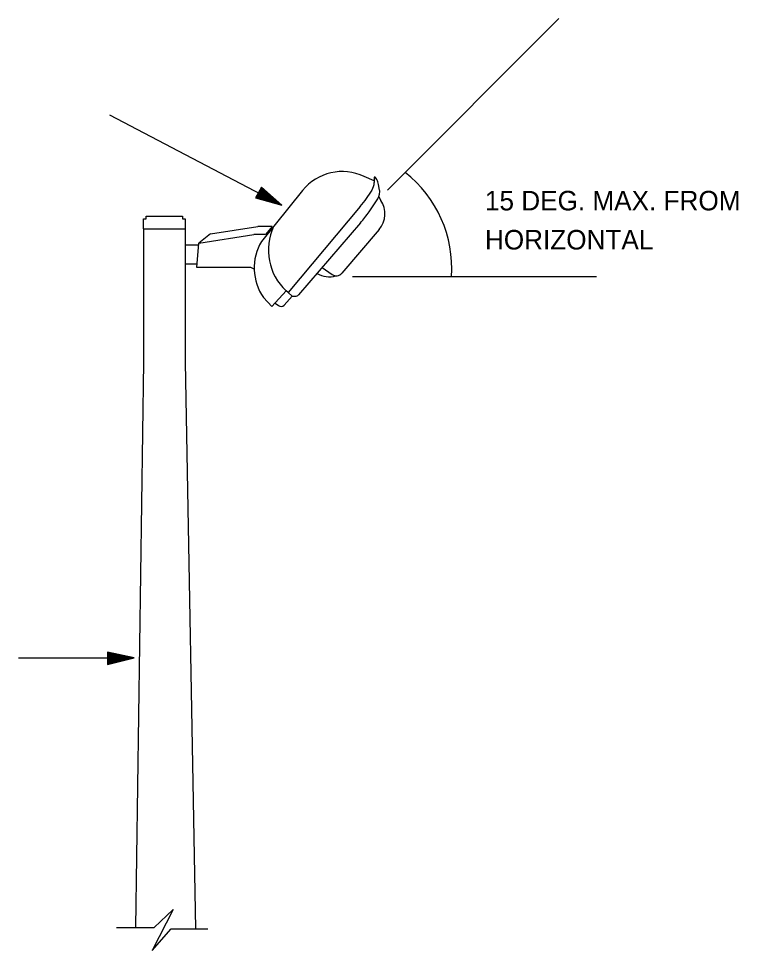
# Model space of a CAD drawing. Extents: x 9989.4 to 10000.1, y 10000.3 to 10010.3.
# Drawn here: x 9997.851 to 10000.06, y 10007.312 to 10010.173 of the extents above; entities that cross this region are included whole.
import ezdxf

# ---------------------------------------------------------------- set-up
doc = ezdxf.new("R2010")
doc.units = 0
for name, color, linetype in [('DETL-DIMS', 7, 'Continuous'), ('DETL-LINE', 7, 'Continuous'), ('DETL-NOTE', 7, 'Continuous')]:
    doc.layers.add(name, color=color, linetype=linetype)

msp = doc.modelspace()

# ---------------------------------------------------------------- linework, layer by layer
at = {"layer": 'DETL-DIMS'}
for p, q in [((9998.9831, 10009.6462), (9999.5096, 10010.1727)), ((9998.1296, 10009.877), (9998.6591, 10009.6003)), ((9998.8759, 10009.3805), (9999.625, 10009.3805)), ((9997.8507, 10008.21), (9998.2057, 10008.21))]:
    msp.add_line(p, q, dxfattribs=at)
for points in [[(9998.5776, 10009.6222), (9998.6591, 10009.6003), (9998.5959, 10009.6555), (9998.5776, 10009.6222)], [(9998.5808, 10009.6239), (9998.6521, 10009.6041), (9998.5967, 10009.6528), (9998.5808, 10009.6239)], [(9998.5835, 10009.6247), (9998.6451, 10009.608), (9998.5975, 10009.6501), (9998.5835, 10009.6247)], [(9998.5854, 10009.6259), (9998.6381, 10009.6118), (9998.5969, 10009.647), (9998.5854, 10009.6259)], [(9998.5881, 10009.6267), (9998.6319, 10009.6152), (9998.5977, 10009.6443), (9998.5881, 10009.6267)], [(9998.5913, 10009.6284), (9998.6241, 10009.6195), (9998.5985, 10009.6415), (9998.5913, 10009.6284)], [(9998.594, 10009.6292), (9998.6179, 10009.6229), (9998.5993, 10009.6388), (9998.594, 10009.6292)], [(9998.5958, 10009.6305), (9998.6104, 10009.6259), (9998.5992, 10009.6366), (9998.5958, 10009.6305)], [(9998.5986, 10009.6312), (9998.6034, 10009.6297), (9998.5995, 10009.633), (9998.5986, 10009.6312)], [(9998.1237, 10008.19), (9998.2057, 10008.21), (9998.1237, 10008.228), (9998.1237, 10008.19)], [(9998.1257, 10008.193), (9998.1977, 10008.21), (9998.1257, 10008.226), (9998.1257, 10008.193)], [(9998.1277, 10008.195), (9998.1897, 10008.21), (9998.1277, 10008.224), (9998.1277, 10008.195)], [(9998.1287, 10008.197), (9998.1817, 10008.21), (9998.1287, 10008.221), (9998.1287, 10008.197)], [(9998.1307, 10008.2), (9998.1747, 10008.21), (9998.1307, 10008.219), (9998.1307, 10008.2)], [(9998.1327, 10008.202), (9998.1657, 10008.21), (9998.1327, 10008.217), (9998.1327, 10008.202)], [(9998.1347, 10008.204), (9998.1587, 10008.21), (9998.1347, 10008.215), (9998.1347, 10008.204)], [(9998.1357, 10008.206), (9998.1507, 10008.209), (9998.1357, 10008.213), (9998.1357, 10008.206)], [(9998.1377, 10008.208), (9998.1427, 10008.209), (9998.1377, 10008.21), (9998.1377, 10008.208)]]:
    msp.add_lwpolyline(points, dxfattribs=at)
msp.add_arc((9998.8026, 10009.4044), 0.3781, 356.3696, 51.5784, dxfattribs=at)
at = {"layer": 'DETL-LINE'}
for p, q in [((9998.9419, 10009.6742), (9998.9113, 10009.6885)), ((9998.9421, 10009.6842), (9998.9421, 10009.6691)), ((9998.9503, 10009.6784), (9998.9462, 10009.6854)), ((9998.959, 10009.6462), (9998.9559, 10009.6636)), ((9998.7225, 10009.6449), (9998.596, 10009.4889)), ((9998.9562, 10009.6251), (9998.9631, 10009.6147)), ((9998.8996, 10009.5957), (9998.6777, 10009.3319)), ((9998.9266, 10009.5798), (9998.9498, 10009.6128)), ((9998.2337, 10009.558), (9998.2417, 10009.558)), ((9998.2337, 10009.5276), (9998.2337, 10009.558)), ((9998.2417, 10009.566), (9998.3537, 10009.566)), ((9998.2417, 10009.558), (9998.2417, 10009.566)), ((9998.3537, 10009.566), (9998.3537, 10009.558)), ((9998.3537, 10009.558), (9998.3617, 10009.558)), ((9998.3617, 10009.558), (9998.3617, 10009.5276)), ((9998.9001, 10009.5457), (9998.7099, 10009.3249)), ((9998.2337, 10009.5276), (9998.2337, 10009.118)), ((9998.2337, 10009.5276), (9998.3617, 10009.5276)), ((9998.3617, 10009.5276), (9998.3617, 10009.118)), ((9998.44, 10009.5123), (9998.4042, 10009.4837)), ((9998.4042, 10009.4837), (9998.5731, 10009.5097)), ((9998.44, 10009.5123), (9998.5847, 10009.5346)), ((9998.6084, 10009.5097), (9998.5731, 10009.5097)), ((9998.6294, 10009.5346), (9998.5847, 10009.5346)), ((9998.629, 10009.5346), (9998.6084, 10009.5097)), ((9998.9576, 10009.5256), (9998.8428, 10009.3909)), ((9998.3976, 10009.4088), (9998.4042, 10009.4837)), ((9998.4036, 10009.4767), (9998.3617, 10009.4767)), ((9998.3985, 10009.4185), (9998.3617, 10009.4185)), ((9998.5636, 10009.4088), (9998.3976, 10009.4088)), ((9998.574, 10009.4038), (9998.5636, 10009.4088)), ((9998.7823, 10009.4089), (9998.8137, 10009.3871)), ((9998.6282, 10009.289), (9998.6025, 10009.3163)), ((9998.6718, 10009.3369), (9998.6282, 10009.289)), ((9998.6905, 10009.3204), (9998.6661, 10009.2932)), ((9998.6777, 10009.3319), (9998.6718, 10009.3369)), ((9998.6905, 10009.3204), (9998.6777, 10009.3319)), ((9998.6905, 10009.3204), (9998.7, 10009.3204)), ((9998.638, 10009.2996), (9998.6484, 10009.2916)), ((9998.2337, 10009.118), (9998.2097, 10007.382)), ((9998.3617, 10009.118), (9998.3937, 10007.378))]:
    msp.add_line(p, q, dxfattribs=at)
msp.add_lwpolyline([(9998.1507, 10007.382), (9998.2667, 10007.382), (9998.3247, 10007.437), (9998.2607, 10007.312), (9998.3187, 10007.378), (9998.4317, 10007.378)], dxfattribs=at)
for centre, radius, start, end in [((9998.8448, 10009.5457), 0.1575, 65.0136, 140.9707), ((9998.9443, 10009.6842), 0.00219, 30.9638, 180), ((9998.8984, 10009.6691), 0.0437, 329.0319, 0), ((9998.9128, 10009.6559), 0.0437, 10.1322, 30.9638), ((9998.5983, 10009.8491), 0.3937, 319.9333, 329.0319), ((9998.9069, 10009.643), 0.0525, 324.9234, 358.8093), ((9998.9375, 10009.6423), 0.0219, 358.8093, 10.1322), ((9998.901, 10009.5738), 0.0744, 319.5618, 33.3664), ((9998.5687, 10009.8311), 0.4374, 319.2588, 324.9234), ((9998.7891, 10009.4626), 0.1719, 155.3459, 226.9709), ((9998.7344, 10009.4076), 0.1605, 149.5698, 214.7082), ((9998.8035, 10009.452), 0.0719, 238.8499, 287.1703), ((9998.8262, 10009.4051), 0.0219, 235.292, 319.5618), ((9998.7, 10009.3335), 0.0131, 270, 319.2588), ((9998.6564, 10009.302), 0.0131, 232.4543, 318.117)]:
    msp.add_arc(centre, radius, start, end, dxfattribs=at)

# ---------------------------------------------------------------- texts
at = {"layer": 'DETL-NOTE'}
for s, p in [('15 DEG. MAX. FROM ', (9999.2823, 10009.5839)), ('HORIZONTAL', (9999.2823, 10009.4639))]:
    msp.add_text(s, height=0.06, dxfattribs=at).set_placement(p)

doc.saveas('drawing.dxf')
